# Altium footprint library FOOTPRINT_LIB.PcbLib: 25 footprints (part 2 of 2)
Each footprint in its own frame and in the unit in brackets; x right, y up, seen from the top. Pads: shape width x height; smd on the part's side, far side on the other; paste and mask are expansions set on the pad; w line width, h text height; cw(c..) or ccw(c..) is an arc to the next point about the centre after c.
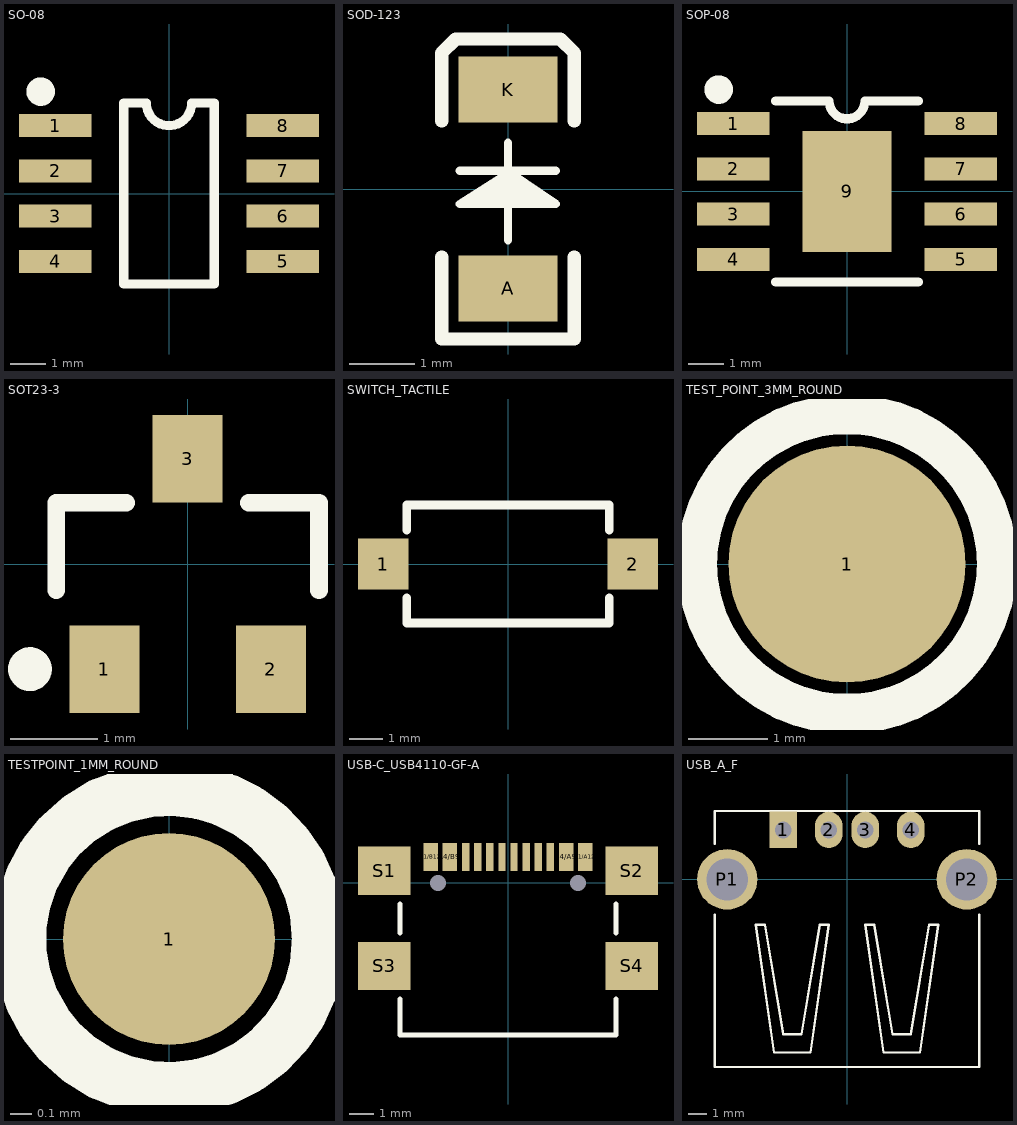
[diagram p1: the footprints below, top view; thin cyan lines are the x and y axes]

## SO-08 [mm]
pads (8):
  rect 2.032x0.65 smd: 1(-3.194,1.905) 2(-3.194,0.635) 3(-3.194,-0.635) 4(-3.194,-1.905) 5(3.194,-1.905) 6(3.194,-0.635) 7(3.194,0.635) 8(3.194,1.905)
Top Overlay:
  circle w0.4: c-3.6,2.86 r0.2
  lines w0.254: -1.27,-2.54 1.27,-2.54 1.27,2.54 0.635,2.54 cw(c0,2.54) -0.635,2.54 -1.27,2.54 -1.27,-2.54
3D body "SOIC8.stp": height 1.9, standoff 0, extent -3.094,-2.505 3.106,2.495

## SOD-123 [mil]
pads (2):
  rect 60x40 smd: A(0,-60) K(0,60)
Top Overlay:
  lines w5: -29.13,10.97 3.87,10.97 ; -20.09,-6 20.91,-6 ; 0,-31 0,-11 ; 0,10 0,28 ; 0.91,10.97 28.91,10.97 ; -29.09,-9 28.91,-9 0.91,10 -29.09,-9
  lines w8: -39.94,-41 -39.94,-90.55 39.94,-90.55 39.94,-41 ; -39.94,41 -39.94,82.11 -31.5,90.55 31.5,90.55 39.94,82.11 39.94,41
  lines w10: -18.09,-6 -0.09,4 15.91,-6 -2.09,-3
3D body "CircuitWorks-SOD123.step": height 50, standoff 0, extent -31.5,-72.83 31.5,72.84

## SOP-08 [mm]
pads (9):
  rect 2.032x0.65 smd: 1(-3.194,1.905) 2(-3.194,0.635) 3(-3.194,-0.635) 4(-3.194,-1.905) 5(3.194,-1.905) 6(3.194,-0.635) 7(3.194,0.635) 8(3.194,1.905)
  rect 2.5x3.4 smd: 9(0,0)
Top Overlay:
  circle w0.4: c-3.6,2.86 r0.2
  lines w0.254: -2,-2.54 2,-2.54 ; -2,2.54 -0.5,2.54 ccw(c0,2.54) 0.5,2.54 2,2.54
3D body "SOIC8.stp": height 1.9, standoff 0, extent -3.094,-2.505 3.106,2.495

## SOT23-3 [mm] "SOT23, 3-Leads, Body 2.90x2.45mm, Pitch 0.95mm, IPC Medium Density"
height 1.1
pads (3):
  rect 0.8x1 smd: 1(-0.95,-1.2) 2(0.95,-1.2) 3(0,1.2)
Top Overlay:
  circle w0.25: c-1.8,-1.2 r0.125
  lines w0.2: -1.5,-0.3 -1.5,0.7 -0.7,0.7 ; 0.7,0.7 1.5,0.7 1.5,-0.3
3D body "SOT95P245X110-3N.step": height 1.1, standoff 0, extent -1.5,-1.3 1.5,1.3

## SWITCH_TACTILE [mm]
pads (2):
  rect 1.5x1.5 smd: 1(-3.7,0) 2(3.7,0)
Top Overlay:
  lines w0.254: -3,-1 -3,-1.75 3,-1.75 3,-1 ; -3,1 -3,1.75 3,1.75 3,1
3D body "Tactile_Switch_SMD.step": height 4.3, standoff 0, extent -4,-1.75 4,1.75

## TEST_POINT_3MM_ROUND [mm]
pads (1):
  round 3 smd: 1(0,0)
Top Overlay:
  circle w0.508: c0,0 r1.9

## TESTPOINT_1MM_ROUND [mm]
pads (1):
  round 1 smd: 1(0,0)
Top Overlay:
  circle w0.254: c0,0 r0.707

## USB-C_USB4110-GF-A [mm]
pads (18):
  rect 0.6x1.15 smd: A1/B12(-3.2,1.075) A4/B9(-2.4,1.075) B1/A12(3.2,1.075) B4/A9(2.4,1.075)
  rect 0.3x1.15 smd: A5(-1.25,1.075) A6(-0.25,1.075) A7(0.25,1.075) A8(1.25,1.075) B5(1.75,1.075) B6(0.75,1.075) B7(-0.75,1.075) B8(-1.75,1.075)
  rect 2.18x2 smd: S1(-5.11,0.5) S2(5.11,0.5) S3(-5.11,-3.43) S4(5.11,-3.43)
  round 0 hole 0.65 unplated: ""(-2.89,0) ""(2.89,0)
Top Overlay:
  lines w0.2: -4.47,-4.79 -4.47,-6.28 4.47,-6.28 4.47,-4.79 ; -4.47,-2.07 -4.47,-0.86 ; 4.47,-2.07 4.47,-0.86
3D body "USB4110-GF-A--3DModel-STEP-56544.STEP": height 3.26, standoff -0.7, extent -5.65,-6.28 5.65,1.4

## USB_A_F [mm]
pads (6):
  rect 1.5x2 hole 0.92: 1(-3.5,2.71)
  oval 1.5x2 hole 0.92: 2(-1,2.71) 3(1,2.71) 4(3.5,2.71)
  round 3.316 hole 2.3: P1(-6.57,0) P2(6.57,0)
Top Overlay:
  lines w0.127: -7.25,-1.95 -7.25,-10.3 7.25,-10.3 7.25,-1.95 ; -7.25,1.95 -7.25,3.75 7.25,3.75 7.25,1.95 ; -5,-2.5 -4.5,-2.5 -3.5,-8.5 -2.5,-8.5 -1.5,-2.5 -1,-2.5 -2,-9.5 -4,-9.5 -5,-2.5 ; 1,-2.5 1.5,-2.5 2.5,-8.5 3.5,-8.5 4.5,-2.5 5,-2.5 4,-9.5 2,-9.5 1,-2.5
3D body "87520-0010BLF--3DModel-STEP-56544.STEP": height 7.8, standoff -2.75, extent -7.25,-10.3 7.25,3.7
